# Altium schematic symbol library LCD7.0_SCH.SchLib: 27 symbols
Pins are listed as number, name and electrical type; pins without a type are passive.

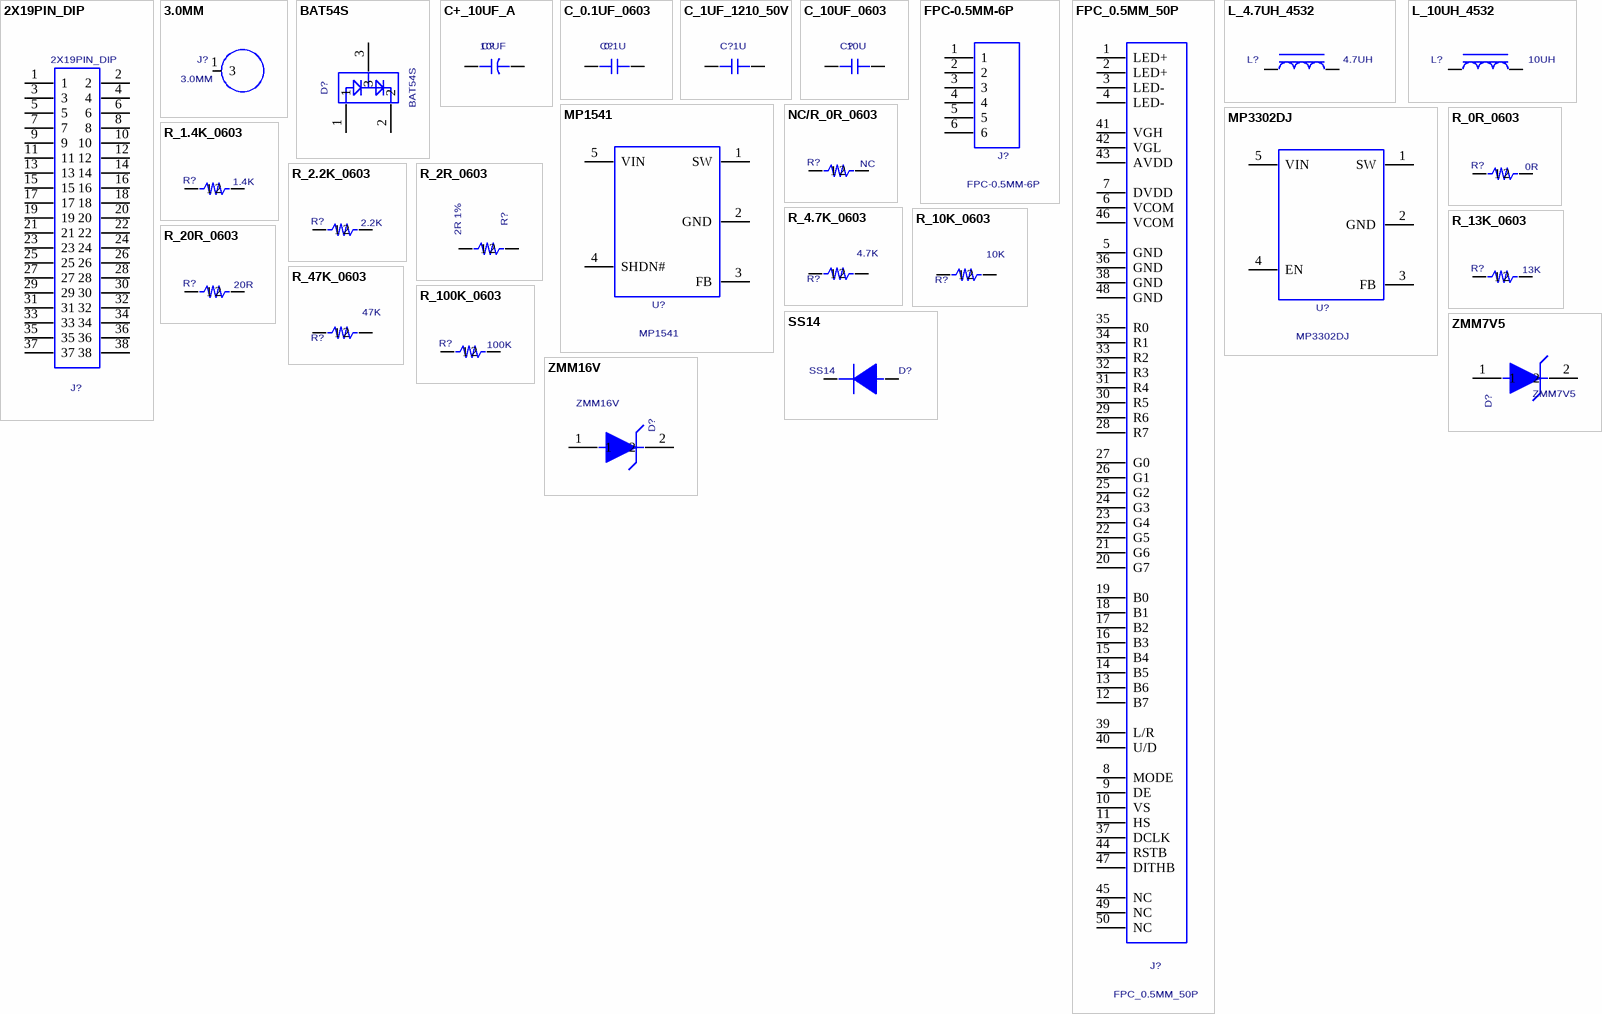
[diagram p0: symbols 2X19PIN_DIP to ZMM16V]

## 2X19PIN_DIP
designator J?
PCB DECAL: 2X19X2.54MM
footprint 2X19X2.54MM
pins: 1, 2, 3, 4, 5, 6, 7, 8, 9, 10, 11, 12, 13, 14, 15, 16, 17, 18, 19, 20, 21, 22, 23, 24, 25, 26, 27, 28, 29, 30, 31, 32, 33, 34, 35, 36, 37, 38

## 3.0MM
designator J?
footprint 3.0MM
pins: 1 3

## BAT54S
designator D?
PCB DECAL: SOT-23
footprint SOT-23
pins: 1, 2, 3

## C+_10UF_A
designator C?  value 10UF  (hidden comment: C+_10UF_A)
PCB DECAL: AVX_A_3216-18
footprint AVX_A_3216-18
pins: 1 +, 2 -

## C_0.1UF_0603
designator C?  value 0.1U  (hidden comment: C_0.1UF_0603)
PCB DECAL: C_0603
footprint C_0603
pins: 1, 2

## C_1UF_1210_50V
designator C?  value 1U  (hidden comment: C_1UF_1210_50V)
PCB DECAL: 1210
footprint 1210
pins: 1, 2

## C_10UF_0603
designator C?  value 10U  (hidden comment: C_10UF_0603)
PCB DECAL: C_0603
footprint C_0603
pins: 1, 2

## FPC-0.5MM-6P
designator J?
PCB DECAL: 6P-FPC-0.5
footprint 6P-FPC-0.5
pins: 1, 2, 3, 4, 5, 6

## FPC_0.5MM_50P
designator J?
footprint FPC_0.5MM_50P
pins: 1 LED+, 2 LED+, 3 LED-, 4 LED-, 5 GND, 6 VCOM, 7 DVDD, 8 MODE, 9 DE, 10 VS, 11 HS, 12 B7, 13 B6, 14 B5, 15 B4, 16 B3, 17 B2, 18 B1, 19 B0, 20 G7, 21 G6, 22 G5, 23 G4, 24 G3, 25 G2, 26 G1, 27 G0, 28 R7, 29 R6, 30 R5, 31 R4, 32 R3, 33 R2, 34 R1, 35 R0, 36 GND, 37 DCLK, 38 GND, 39 L/R, 40 U/D, 41 VGH, 42 VGL, 43 AVDD, 44 RSTB, 45 NC, 46 VCOM, 47 DITHB, 48 GND, 49 NC, 50 NC

## L_4.7UH_4532
designator L?  value 4.7UH  (hidden comment: L_4.7UH_4532)
PCB DECAL: GDCD4532
footprint GDCD4532
pins: 1, 2

## L_10UH_4532
designator L?  value 10UH  (hidden comment: L_10UH_4532)
PCB DECAL: GDCD4532
footprint GDCD4532
pins: 1, 2

## MP1541
designator U?
PCB DECAL: SOT-23-5
footprint SOT-23-5
pins: 1 SW, 2 GND, 3 FB, 4 SHDN#, 5 VIN

## MP3302DJ
designator U?
PCB DECAL: SOT-23-5
footprint SOT-23-5
pins: 1 SW, 2 GND, 3 FB, 4 EN, 5 VIN

## NC/R_0R_0603
designator R?  value NC  (hidden comment: NC/R_0R_0603)
PCB DECAL: R_0603
footprint R_0603
pins: 1, 2

## R_0R_0603
designator R?  value 0R  (hidden comment: R_0R_0603)
PCB DECAL: R_0603
footprint R_0603
pins: 1, 2

## R_1.4K_0603
designator R?  value 1.4K  (hidden comment: R_1.4K_0603)
PCB DECAL: R_0603
footprint R_0603
pins: 1, 2

## R_2.2K_0603
designator R?  value 2.2K  (hidden comment: R_2.2K_0603)
PCB DECAL: R_0603
footprint R_0603
pins: 1, 2

## R_2R_0603
designator R?  value 2R 1%  (hidden comment: R_2R_0603)
PCB DECAL: R_0603
footprint R_0603
pins: 1, 2

## R_4.7K_0603
designator R?  value 4.7K  (hidden comment: R_4.7K_0603)
PCB DECAL: R_0603
footprint R_0603
pins: 1, 2

## R_10K_0603
designator R?  value 10K  (hidden comment: R_10K_0603)
PCB DECAL: R_0603
footprint R_0603
pins: 1, 2

## R_13K_0603
designator R?  value 13K  (hidden comment: R_13K_0603)
PCB DECAL: R_0603
footprint R_0603
pins: 1, 2

## R_20R_0603
designator R?  value 20R  (hidden comment: R_20R_0603)
PCB DECAL: R_0603
footprint R_0603
pins: 1, 2

## R_47K_0603
designator R?  value 47K  (hidden comment: R_47K_0603)
PCB DECAL: R_0603
footprint R_0603
pins: 1, 2

## R_100K_0603
designator R?  value 100K  (hidden comment: R_100K_0603)
PCB DECAL: R_0603
footprint R_0603
pins: 1, 2

## SS14
designator D?
PCB DECAL: SS24_1206
footprint SS24_1206
pins: 1 +, 2 -

## ZMM7V5
designator D?
PCB DECAL: ZMM4V3
footprint ZMM4V3
pins: 1, 2

## ZMM16V
designator D?
PCB DECAL: ZMM4V3
footprint ZMM4V3
pins: 1, 2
